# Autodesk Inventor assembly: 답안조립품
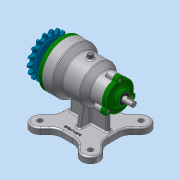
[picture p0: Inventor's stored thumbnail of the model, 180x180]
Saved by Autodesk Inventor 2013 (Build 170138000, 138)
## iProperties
Created: 2017-03
Part Number: 답안조립품
Document SubType Name: Assembly
Designer: dgall
Author: dgall
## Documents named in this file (14)
- C:\Users\dgall\Desktop\470307V1010\답안조립품.iam
- C:\Users\dgall\Desktop\470307V1010\본체1.ipt
- C:\Users\dgall\Desktop\470307V1010\뒤커버.ipt
- C:\Users\dgall\Desktop\470307V1010\앞커버.ipt
- C:\Users\dgall\Desktop\470307V1010\축.ipt
- C:\Users\dgall\Desktop\470307V1010\베어링-6200.ipt
- C:\Users\dgall\Desktop\470307V1010\베어링-6203.ipt
- C:\Users\dgall\Desktop\470307V1010\스프로킷.ipt
- C:\Users\dgall\Desktop\470307V1010\키5x5.ipt
- C:\Users\dgall\Desktop\470307V1010\오일 실 10 20 7.ipt
- C:\Users\dgall\Desktop\470307V1010\오일 실 17 30 8.ipt
- C:\Users\dgall\Desktop\470307V1010\볼트 M4 x 12.ipt
- C:\Users\dgall\Desktop\470307V1010\볼트 M5 x 10.ipt
- 볼트 M5 x 10.ipt
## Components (9 placed, 1 different names)
1. ISO 4762 M4 x 12:2
2. ISO 4762 M4 x 12:3
3. ISO 4762 M4 x 12:4
4. ISO 4762 M4 x 12:1
5. ISO 4762 M4 x 12:5
6. ISO 4762 M4 x 12:6
7. ISO 4762 M4 x 12:7
8. ISO 4762 M4 x 12:8
9. ISO 4762 M4 x 12:9
